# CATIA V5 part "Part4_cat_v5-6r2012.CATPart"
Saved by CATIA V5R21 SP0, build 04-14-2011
Part number: Guide
Bounding box of the stored display mesh (mm): x -5 to 5, y -5 to 5, z -25 to 25
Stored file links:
  D:\CATIA V5R21 E-RESOURCES\CATIA-V5R21\catia-v5r21-Tut\c16-catia-v5r21-tut\c16-catia-v5r21-tut03\Part4_cat_v5r21.CATPart
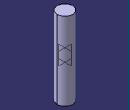
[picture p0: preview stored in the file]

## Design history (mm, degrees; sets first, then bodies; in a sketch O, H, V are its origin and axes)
Body1 (main body)
  Sketch1 on xy-plane, origin (0, 0, 0), H (1, 0, 0), V (0, 1, 0)
    circle A1 centre (0, 0) radius 5
    radius A1 = 5
  Pad1: profile Sketch1, direction (0, 0, 1), length 25, mirrored extent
